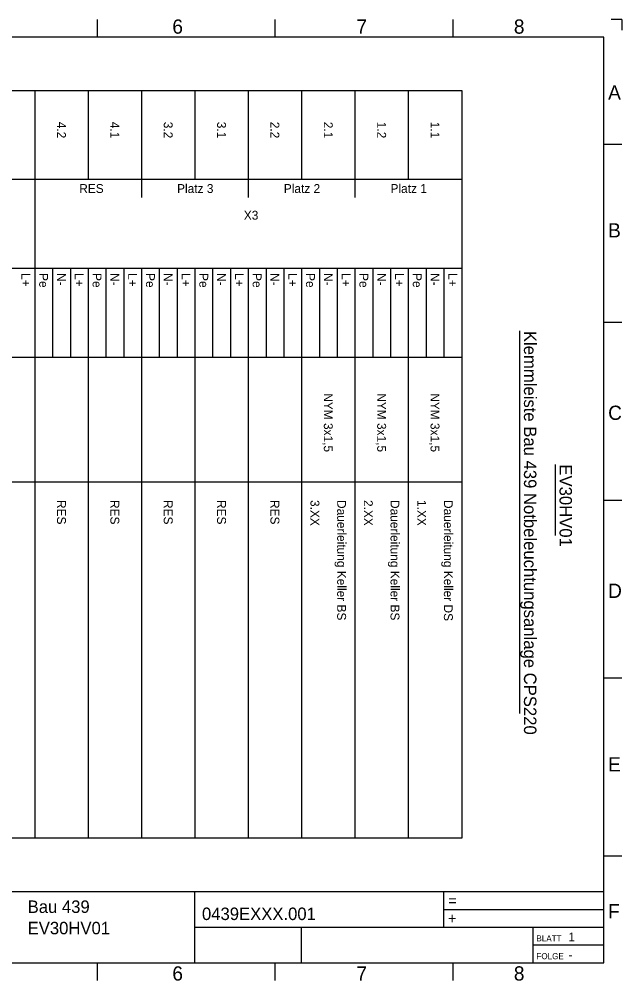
# Model space of a CAD drawing. Extents: x 0 to 395, y 0 to 270.
# Drawn here: x 225.6 to 395, y -0.1 to 270.1 of the extents above; entities that cross this region are included whole.
import ezdxf

# ---------------------------------------------------------------- set-up
doc = ezdxf.new("R2010")
doc.units = 0
for name, color, linetype in [('30_Graphik', 7, 'Continuous'), ('30_Text', 7, 'Continuous'), ('90_Plankopf', 7, 'Continuous')]:
    doc.layers.add(name, color=color, linetype=linetype)

msp = doc.modelspace()

# ---------------------------------------------------------------- linework, layer by layer
at = {"layer": '30_Graphik'}
for p, q in [((20, 250), (350, 250)), ((230, 250), (230, 40)), ((245, 250), (245, 225)), ((260, 250), (260, 220)), ((275, 250), (275, 225)), ((290, 250), (290, 220)), ((305, 250), (305, 225)), ((320, 250), (320, 220)), ((335, 250), (335, 225)), ((350, 250), (350, 40)), ((350, 225), (20, 225)), ((350, 200), (20, 200)), ((235, 200), (235, 175)), ((240, 200), (240, 175)), ((245, 200), (245, 40)), ((250, 200), (250, 175)), ((255, 200), (255, 175)), ((260, 200), (260, 40)), ((265, 200), (265, 175)), ((270, 200), (270, 175)), ((275, 200), (275, 40)), ((280, 200), (280, 175)), ((285, 200), (285, 175)), ((290, 200), (290, 40)), ((295, 200), (295, 175)), ((300, 200), (300, 175)), ((305, 200), (305, 40)), ((310, 200), (310, 175)), ((315, 200), (315, 175)), ((320, 200), (320, 40)), ((325, 200), (325, 175)), ((330, 200), (330, 175)), ((335, 200), (335, 40)), ((340, 200), (340, 175)), ((345, 200), (345, 175)), ((350, 175), (20, 175)), ((350, 140), (20, 140)), ((350, 40), (20, 40))]:
    msp.add_line(p, q, dxfattribs=at)
at = {"layer": '30_Text'}
for p, q in [((366.25, 182.5), (366.25, 75)), ((376.25, 145), (376.25, 125))]:
    msp.add_line(p, q, dxfattribs=at)
at = {"layer": '90_Plankopf'}
for p, q in [((247.5, 270), (247.5, 265)), ((297.5, 270), (297.5, 265)), ((347.5, 270), (347.5, 265)), ((395, 270), (392, 270)), ((395, 270), (395, 267)), ((390, 265), (5, 265)), ((390, 5), (390, 265)), ((390, 235), (395, 235)), ((390, 185), (395, 185)), ((390, 135), (395, 135)), ((390, 85), (395, 85)), ((390, 35), (395, 35)), ((5, 25), (390, 25)), ((275, 5), (275, 25)), ((345, 15), (345, 25)), ((345, 20), (390, 20)), ((275, 15), (390, 15)), ((305, 5), (305, 15)), ((370, 15), (370, 5)), ((370, 10), (390, 10)), ((5, 5), (390, 5)), ((247.5, 5), (247.5, 0)), ((297.5, 5), (297.5, 0)), ((347.5, 5), (347.5, 0))]:
    msp.add_line(p, q, dxfattribs=at)

# ---------------------------------------------------------------- texts
at = {"layer": '30_Text'}
for s, height, rotation, p in [('4.2', 2.5, 270, (236.25, 241.25)), ('4.1', 2.5, 270, (251.25, 241.25)), ('3.2', 2.5, 270, (266.25, 241.25)), ('3.1', 2.5, 270, (281.25, 241.25)), ('2.2', 2.5, 270, (296.25, 241.25)), ('2.1', 2.5, 270, (311.25, 241.25)), ('1.2', 2.5, 270, (326.25, 241.25)), ('1.1', 2.5, 270, (341.25, 241.25)), ('RES', 2.5, 360, (242.5, 221.25)), ('Platz 3', 2.5, 360, (270, 221.25)), ('Platz 2', 2.5, 360, (300, 221.25)), ('L+', 2.5, 270, (226.25, 198.75)), ('Pe', 2.5, 270, (231.25, 198.75)), ('N-', 2.5, 270, (236.25, 198.75)), ('L+', 2.5, 270, (241.25, 198.75)), ('Pe', 2.5, 270, (246.25, 198.75)), ('N-', 2.5, 270, (251.25, 198.75)), ('L+', 2.5, 270, (256.25, 198.75)), ('Pe', 2.5, 270, (261.25, 198.75)), ('N-', 2.5, 270, (266.25, 198.75)), ('L+', 2.5, 270, (271.25, 198.75)), ('Pe', 2.5, 270, (276.25, 198.75)), ('N-', 2.5, 270, (281.25, 198.75)), ('L+', 2.5, 270, (286.25, 198.75)), ('Pe', 2.5, 270, (291.25, 198.75)), ('N-', 2.5, 270, (296.25, 198.75)), ('L+', 2.5, 270, (301.25, 198.75)), ('Pe', 2.5, 270, (306.25, 198.75)), ('N-', 2.5, 270, (311.25, 198.75)), ('L+', 2.5, 270, (316.25, 198.75)), ('Pe', 2.5, 270, (321.25, 198.75)), ('N-', 2.5, 270, (326.25, 198.75)), ('L+', 2.5, 270, (331.25, 198.75)), ('Pe', 2.5, 270, (336.25, 198.75)), ('N-', 2.5, 270, (341.25, 198.75)), ('L+', 2.5, 270, (346.25, 198.75)), ('Klemmleiste Bau 439 Notbeleuchtungsanlage CPS220', 3.5, 270, (367.5, 182.5)), ('NYM 3x1,5', 2.5, 270, (311.25, 165)), ('NYM 3x1,5', 2.5, 270, (326.25, 165)), ('NYM 3x1,5', 2.5, 270, (341.25, 165)), ('EV30HV01', 3.5, 270, (377.5, 145)), ('RES', 2.5, 270, (236.25, 135)), ('RES', 2.5, 270, (251.25, 135)), ('RES', 2.5, 270, (266.25, 135)), ('RES', 2.5, 270, (281.25, 135)), ('RES', 2.5, 270, (296.25, 135)), ('3.XX', 2.5, 270, (307.5, 135)), ('Dauerleitung Keller BS', 2.5, 270, (315, 135)), ('2.XX', 2.5, 270, (322.5, 135)), ('Dauerleitung Keller BS', 2.5, 270, (330, 135)), ('1.XX', 2.5, 270, (337.5, 135)), ('Dauerleitung Keller DS', 2.5, 270, (345, 135))]:
    msp.add_text(s, height=height, rotation=rotation, dxfattribs=at).set_placement(p)
for s, p in [('Platz 1', (330, 221.25)), ('X3', (288.75, 213.75))]:
    msp.add_text(s, height=2.5, dxfattribs=at).set_placement(p)
at = {"layer": '90_Plankopf'}
for s, height, p in [('6', 4, (268.67, 266)), ('7', 4, (320.42, 266)), ('8', 4, (364.67, 266)), ('A', 4, (391.17, 247.5)), ('B', 4, (391.17, 208.75)), ('C', 4, (391.17, 157.5)), ('D', 4, (391.17, 107.5)), ('E', 4, (391.17, 58.75)), ('Bau 439             ', 3.5, (228, 19)), ('=', 3, (346.26, 21)), ('0439EXXX.001        ', 3.5, (277, 17)), ('F', 4, (391.17, 17.5)), ('EV30HV01            ', 3.5, (228, 13)), ('+', 3, (346.19, 16)), ('BLATT', 1.7, (371, 11)), ('1    ', 2.5, (380, 11)), ('FOLGE', 1.7, (371, 6)), ('-    ', 2.5, (380, 6)), ('6', 4, (268.67, 0)), ('7', 4, (320.42, 0)), ('8', 4, (364.67, 0))]:
    msp.add_text(s, height=height, dxfattribs=at).set_placement(p)

doc.saveas('drawing.dxf')
